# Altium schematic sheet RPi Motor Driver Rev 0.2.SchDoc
size C; GateName_1: G$1; SymbolName_1: FRAME_A3_ADAFRUIT; LibraryName: microbuilder; DeviceSetName: FRAME_A3_ADAFRUIT; Organization: Altium Limited; Address1: L3, 12a Rodborough Rd; Address2: Frenchs Forest; Address3: NSW; Address4: Australia 2086
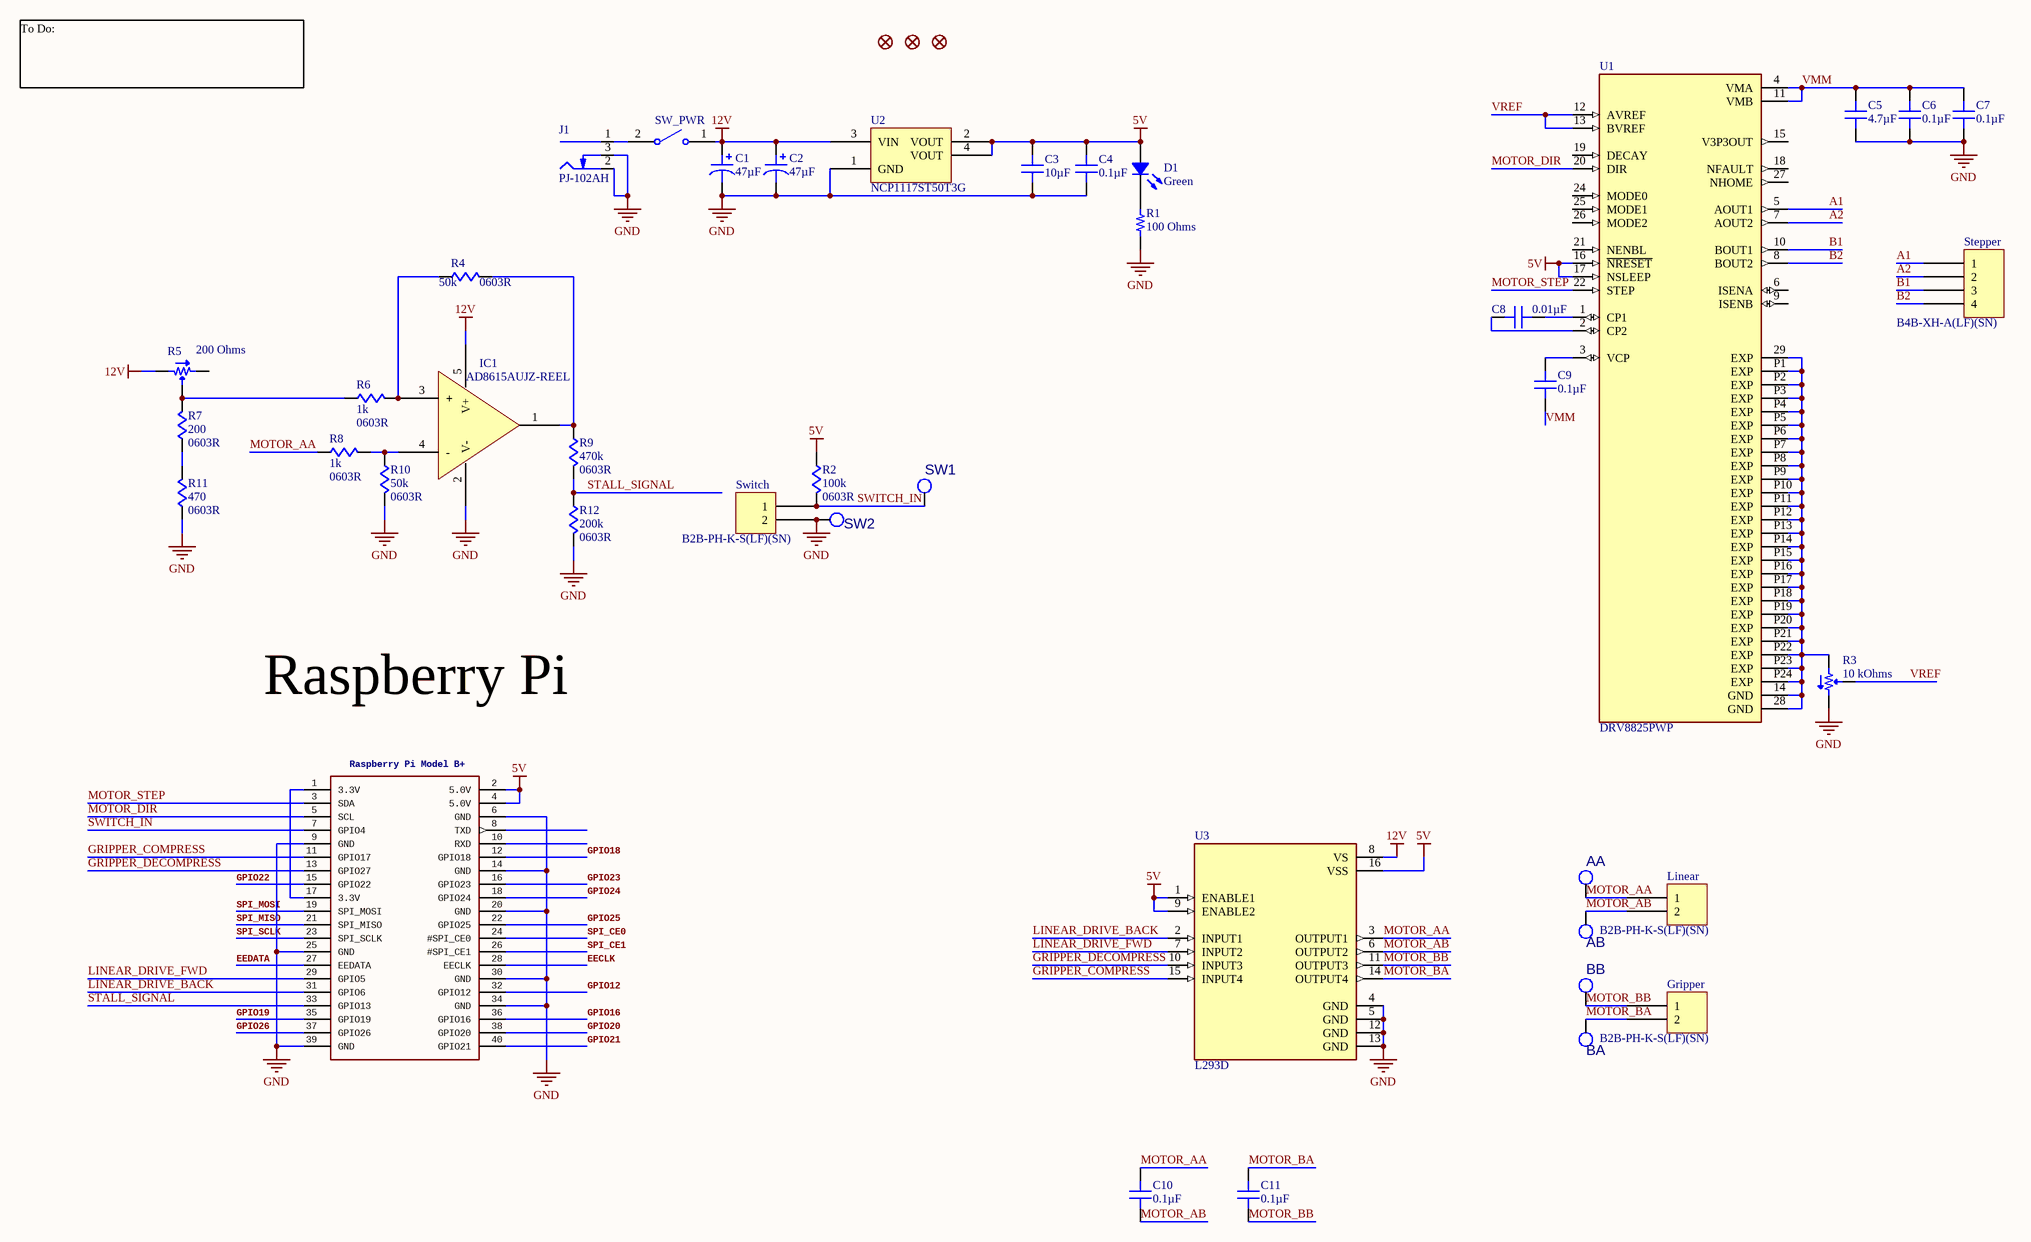
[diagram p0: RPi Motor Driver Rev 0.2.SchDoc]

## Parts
AA  TH_Testpoint_40mil  [TH_Testpoint_40mil]  (value not drawn)
AB  TH_Testpoint_40mil  [TH_Testpoint_40mil]  (value not drawn)
BA  TH_Testpoint_40mil  [TH_Testpoint_40mil]  (value not drawn)
BB  TH_Testpoint_40mil  [TH_Testpoint_40mil]  (value not drawn)
C1  47µF  [CAP ALSMD 6.6MM H6.1MM]
C2  47µF  [CAP ALSMD 6.6MM H6.1MM]
C3  10µF  [CAP 0805_2012]
C4  0.1µF  [CAP 0603_1608]
C5  4.7µF  [CAP 0603_1608]
C6  0.1µF  [CAP 0603_1608]
C7  0.1µF  [CAP 0603_1608]
C8  0.01µF  [CAP 0603_1608]
C9  0.1µF  [CAP 0603_1608]
C10  0.1µF  [CAP 0603_1608]
C11  0.1µF  [CAP 0603_1608]
D1  Green  [LED 0603_1608 GREEN]
FID1  FIDUCIAL""  [FIDUCIAL_1MM]  (value not drawn)
FID2  FIDUCIAL""  [FIDUCIAL_1MM]  (value not drawn)
FID3  FIDUCIAL""  [FIDUCIAL_1MM]  (value not drawn)
Gripper  B2B-PH-K-S(LF)(SN)  [JST B2B-PH-K]
IC1  AD8615AUJZ-REEL  [ANALOG TSOT-23-5 UJ-5]
J1  PJ-102AH  [CUI PJ-102AH]
Linear  B2B-PH-K-S(LF)(SN)  [JST B2B-PH-K]
R1  100 Ohms  [RES 0603_1608]
R2  value 100k  [0603R]  (hidden comment: Resistor 0603)
R3  10 kOhms  [POT BOURNS TRIMPOT TC33]
R4  value 50k  [0603R]  (hidden comment: Resistor 0603)
R5  200 Ohms  [POT BOURNS TRIMPOT TC33]
R6  value 1k  [0603R]  (hidden comment: Resistor 0603)
R7  value 200  [0603R]  (hidden comment: Resistor 0603)
R8  value 1k  [0603R]  (hidden comment: Resistor 0603)
R9  value 470k  [0603R]  (hidden comment: Resistor 0603)
R10  value 50k  [0603R]  (hidden comment: Resistor 0603)
R11  value 470  [0603R]  (hidden comment: Resistor 0603)
R12  value 200k  [0603R]  (hidden comment: Resistor 0603)
RPI1  RaspberryPiModelB+: Raspberry Pi Model B+  [PI_HAT_SLOTS]  (hidden comment: RASPBERRYPI_BPLUS_HATSLOTS)
Stepper  B4B-XH-A(LF)(SN)  [JST XH B4B-XH-A]
SW1  TH_Testpoint_40mil  [TH_Testpoint_40mil]  (value not drawn)
SW2  TH_Testpoint_40mil  [TH_Testpoint_40mil]  (value not drawn)
SW_PWR  48ASSP3S1M2QBT  [SWITCH SLIDE SPDT 5A 125V]  (value not drawn)
Switch  B2B-PH-K-S(LF)(SN)  [JST B2B-PH-K]
U1  DRV8825PWP  [SOP65P640X120-29N]
U2  NCP1117ST50T3G  [ON SEMI SOT-223 ST(318H)]
U3  L293D  [DIP880W50P254L2000H510Q16]

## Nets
5V: C3.2 C4.2 D1.1 R2.2 RPI1.2(5.0V) RPI1.4(5.0V) U1.16(~{NRESET}) U1.17(NSLEEP) U2.2(VOUT) U2.4(VOUT) U3.1(ENABLE1) U3.9(ENABLE2) U3.16(VSS)
12V: C1.1 C2.1 IC1.5(V+) R5.1 SW_PWR.1 U2.3(VIN) U3.8(VS)
GND: C1.2 C2.2 C3.1 C4.1 C5.1 C6.1 C7.1 IC1.2(V-) J1.2(Outer) J1.3(SW) R1.1 R3.3 R10.1 R11.2 R12.1 RPI1.6(GND) RPI1.9(GND) RPI1.14(GND) RPI1.20(GND) RPI1.25(GND) RPI1.30(GND) RPI1.34(GND) RPI1.39(GND) SW2.1 Switch.2 U2.1(GND) U3.4(GND) U3.5(GND) U3.12(GND) U3.13(GND)
A1: Stepper.1 U1.5(AOUT1)
A2: Stepper.2 U1.7(AOUT2)
B1: Stepper.3 U1.10(BOUT1)
B2: Stepper.4 U1.8(BOUT2)
EECLK: RPI1.28(EECLK)
EEDATA: RPI1.27(EEDATA)
GPIO12: RPI1.32(GPIO12)
GPIO16: RPI1.36(GPIO16)
GPIO18: RPI1.12(GPIO18)
GPIO19: RPI1.35(GPIO19)
GPIO20: RPI1.38(GPIO20)
GPIO21: RPI1.40(GPIO21)
GPIO22: RPI1.15(GPIO22)
GPIO23: RPI1.16(GPIO23)
GPIO24: RPI1.18(GPIO24)
GPIO25: RPI1.22(GPIO25)
GPIO26: RPI1.37(GPIO26)
GRIPPER_COMPRESS: RPI1.11(GPIO17) U3.15(INPUT4)
GRIPPER_DECOMPRESS: RPI1.13(GPIO27) U3.10(INPUT3)
LINEAR_DRIVE_BACK: RPI1.31(GPIO6) U3.2(INPUT1)
LINEAR_DRIVE_FWD: RPI1.29(GPIO5) U3.7(INPUT2)
MOTOR_AA: AA.1 C10.2 Linear.1 R8.2 U3.3(OUTPUT1)
MOTOR_AB: AB.1 C10.1 Linear.2 U3.6(OUTPUT2)
MOTOR_BA: BA.1 C11.2 Gripper.2 U3.14(OUTPUT4)
MOTOR_BB: BB.1 C11.1 Gripper.1 U3.11(OUTPUT3)
MOTOR_DIR: RPI1.5(SCL) U1.20(DIR)
MOTOR_STEP: RPI1.3(SDA) U1.22(STEP)
SPI_CE0: RPI1.24(#SPI_CE0)
SPI_CE1: RPI1.26(#SPI_CE1)
SPI_MISO: RPI1.21(SPI_MISO)
SPI_MOSI: RPI1.19(SPI_MOSI)
SPI_SCLK: RPI1.23(SPI_SCLK)
STALL_SIGNAL: R9.1 R12.2 RPI1.33(GPIO13)
SWITCH_IN: R2.1 RPI1.7(GPIO4) SW1.1 Switch.1
VMM: C5.2 C6.2 C7.2 C9.1 U1.4(VMA) U1.11(VMB)
VREF: R3.2 U1.12(AVREF) U1.13(BVREF)
NetC8_1: C8.1 U1.2(CP2)
NetC8_2: C8.2 U1.1(CP1)
NetC9_2: C9.2 U1.3(VCP)
NetD1_2: D1.2 R1.2
NetIC1_1: IC1.1(OUT) R4.1 R9.2
NetIC1_3: IC1.3(+) R4.2 R6.1
NetIC1_4: IC1.4(-) R8.1 R10.2
NetJ1_1: J1.1(Centre) SW_PWR.2
NetR3_1: R3.1 U1.14(GND) U1.28(GND) U1.29(EXP) U1.P1(EXP) U1.P2(EXP) U1.P3(EXP) U1.P4(EXP) U1.P5(EXP) U1.P6(EXP) U1.P7(EXP) U1.P8(EXP) U1.P9(EXP) U1.P10(EXP) U1.P11(EXP) U1.P12(EXP) U1.P13(EXP) U1.P14(EXP) U1.P15(EXP) U1.P16(EXP) U1.P17(EXP) U1.P18(EXP) U1.P19(EXP) U1.P20(EXP) U1.P21(EXP) U1.P22(EXP) U1.P23(EXP) U1.P24(EXP)
NetR5_2: R5.2 R6.2 R7.1
NetR7_2: R7.2 R11.1
NetRPI1_1: RPI1.1(3.3V) RPI1.17(3.3V)

Not connected (* = marked no-connect by the designer): R5 3; RPI1 8(TXD) 10(RXD); U1 6(ISENA) 9(ISENB) 15(V3P3OUT) 18(NFAULT) 19(DECAY) 21(NENBL) 24(MODE0) 25(MODE1) 26(MODE2) 27(NHOME)

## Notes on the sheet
- To Do:
- Raspberry Pi

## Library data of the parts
AA AB BA BB SW1 SW2 = TH_Testpoint_40mil: TH Testpoint
C1 C2 = UCD1V470MCL1GS: CAP ALUM 47UF 20% 35V SMD; Part Number: EEE-FP1V470AP; Manufacturer: Nichicon; Impedance: 360 mOhms; Lifetime @ Temp.: 2000 Hrs @ 105°C; Polarization: Polar; Ripple Current @ High Frequency: 240mA @ 100kHz; Ripple Current @ Low Frequency: 120mA @ 120Hz; Surface Mount Land Size: 0.260" L x 0.260" W (6.60mm x 6.60mm)
C3 = C2012X5R1E106K085AC: CAP CER 10UF 25V X5R 0805; Manufacturer: TDK Corporation; Tolerance: ±10%
C4 C6 C7 C9-C11 = CGA3E2X7R1H104K080AE: CAP CER 0.1UF 50V X7R 0603; Manufacturer: TDK Corporation; Tolerance: ±10%
C5 = C1608X5R1V475M080AC: CAP CER 4.7UF 35V X5R 0603; Manufacturer: TDK Corporation; Tolerance: ±20%
C8 = C0603C103KARACAUTO: CAP CER 0.01UF 250V X7R 0603; Manufacturer: KEMET; Tolerance: ±10%
D1 = APHD1608LCGCK: LED GREEN CLEAR 1608 SMD; Part Number: APT1608CGCK; Manufacturer: Kingbright; Configuration: Standard; Current - Test: 2mA; Lens Color: Colorless; Lens Size: 0.70mm Dia; Lens Style: Round with Domed Top; Millicandela Rating: 5mcd; Viewing Angle: 100°; Voltage - Forward (Vf) (Typ): 1.9V; Wavelength - Dominant: 570nm; Wavelength - Peak: 574nm
FID1-FID3 = FIDUCIAL"": Fiducial Alignment PointsVarious fiducial points for machine vision alignment.; GateName_1: G$1; DeviceName: ""; BOM: EXCLUDE
Gripper Linear Switch = B2B-PH-K-S(LF)(SN): CONN HEADER VERT 2POS 2MM; Manufacturer: JST Sales America Inc.; Contact Length - Mating: 0.130" (3.30mm); Contact Length - Post: 0.134" (3.40mm); Current Rating (Amps): 2A; Material Flammability Rating: UL94 V-0; Number of Positions: 2; Number of Positions Loaded: All; Overall Contact Length: 0.333" (8.45mm); Pitch - Mating: 0.079" (2.00mm); Shrouding: Shrouded - 4 Wall; Style: Board to Cable/Wire; Voltage Rating: 100V
IC1 = AD8615AUJZ-REEL: IC OPAMP GP 1 CIRCUIT TSOT23-5; Manufacturer: Analog Devices Inc.; Amplifier Type: General Purpose; Current - Input Bias: 0.2pA; Current - Output / Channel: 150mA; Current - Supply: 1.7mA; Gain Bandwidth Product: 24MHz; Number of Circuits: 1; Output Type: Rail-to-Rail; Slew Rate: 12V/µs; Voltage - Input Offset: 23µV; Voltage - Supply, Single/Dual (±): 2.7V ~ 5.5V, ±1.35V ~ 2.75V
J1 = PJ-102AH: CONN PWR JACK 2X5.5MM SOLDER; Manufacturer: CUI Devices; Actual Diameter: 0.079" (2.00mm ID), 0.256" (6.50mm OD); Current Rating (Amps): 5A; Gender: Male; Industry Recognized Mating Diameter: 2.00mm ID (0.079"), 5.50mm OD (0.217"); Internal Switch(s): Single Switch, Normally Closed; Material Flammability Rating: UL94 V-0; Mating Length/Depth: 0.354" (9.00mm); Number of Positions/Contacts: 2 Conductors, 3 Contacts; Shielding: Unshielded; Voltage - Rated: 24VDC
R1 = RNCS0603BKE100R: RES 100 OHM 0.1% 1/16W 0603; Manufacturer: Stackpole Electronics Inc; Power (Watts): 0.063W, 1/16W; Temperature Coefficient: ±25ppm/°C
R2 R4 R6-R12 = Resistor
R3 = TC33X-2-103E: TRIMMER 10K OHM 0.1W J LEAD TOP; Manufacturer: Bourns Inc.; Adjustment Type: Top Adjustment; Number of Turns: 1; Power (Watts): 0.1W, 1/10W; Resistive Material: Cermet; Temperature Coefficient: ±250ppm/°C; Tolerance: ±25%
R5 = TC33X-2-201E: TRIMMER 200 OHM 0.1W J LEAD TOP; Manufacturer: Bourns Inc.; Adjustment Type: Top Adjustment; Number of Turns: 1; Power (Watts): 0.1W, 1/10W; Resistive Material: Cermet; Temperature Coefficient: ±250ppm/°C; Tolerance: ±25%
RPI1 = RASPBERRYPI_BPLUS_HATSLOTS: GateName_1: G$1
Stepper = B4B-XH-A(LF)(SN): CONN HEADER VERT 4POS 2.5MM; Manufacturer: JST Sales America Inc.; Contact Length - Post: 0.134" (3.40mm); Current Rating (Amps): 3A; Material Flammability Rating: UL94 V-0; Number of Positions: 4; Number of Positions Loaded: All; Pitch - Mating: 0.098" (2.50mm); Shrouding: Shrouded - 4 Wall; Style: Board to Cable/Wire; Voltage Rating: 250V
SW_PWR = SWITCH SLIDE SPDT 5A 125V
U1 = DRV8825PWP: Bipolar Motor Driver Power MOSFET Logic 28-HTSSOP; MF: Texas Instruments
U2 = NCP1117ST50T3G: IC REG LINEAR 5V 1A SOT223; Manufacturer: ON Semiconductor; Current - Quiescent (Iq): 10mA; Number of Regulators: 1; Output Configuration: Positive; Output Type: Fixed; Protection Features: Over Current, Over Temperature; PSRR: 61dB (120Hz); Voltage Dropout (Max): 1.2V @ 800mA; Voltage - Input (Max): 20V
U3 = L293D: Bipolar Motor Driver Parallel 16-PowerDIP; MF: STMicroelectronics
